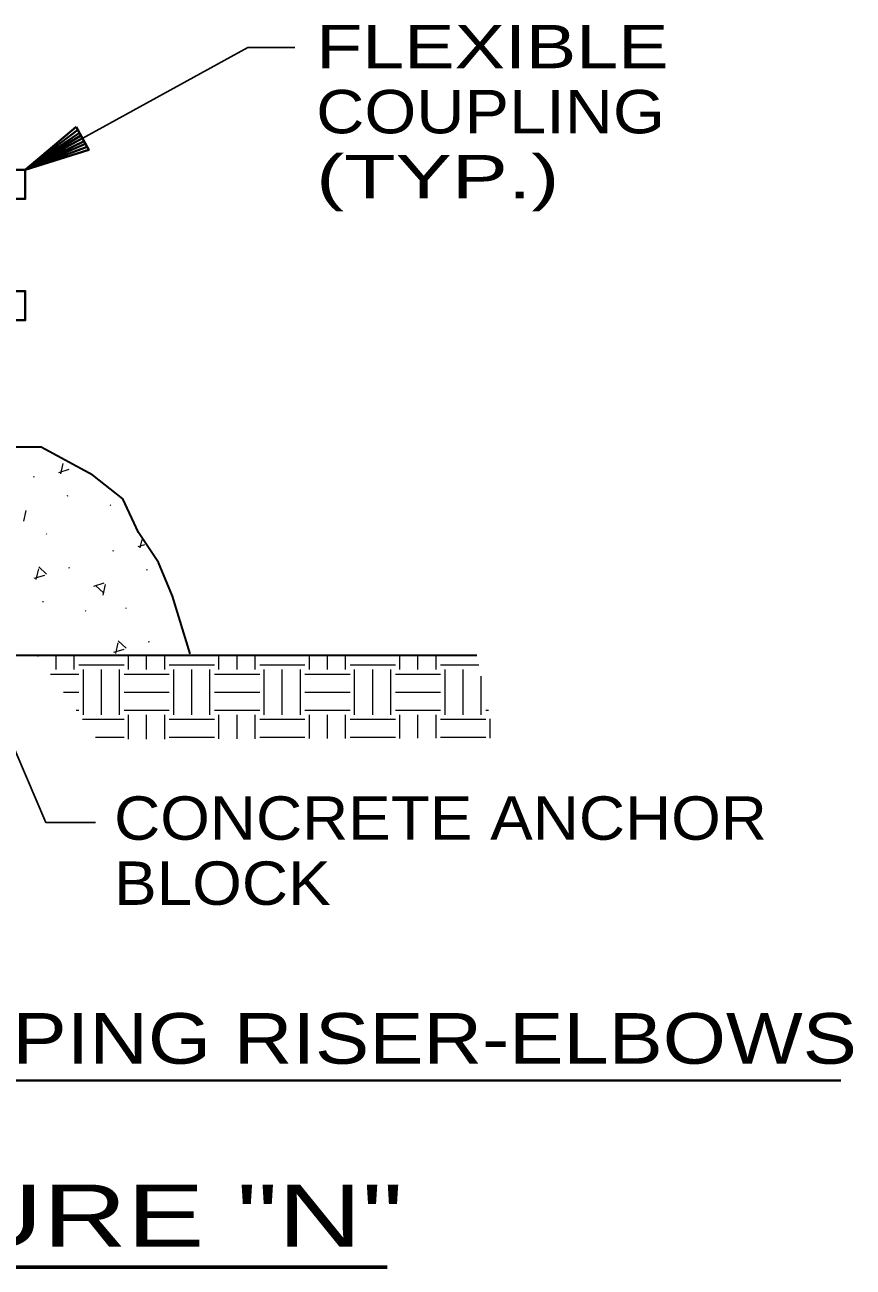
# Model space of a CAD drawing. Extents: x 55 to 190, y 198 to 264.
# Drawn here: x 95.8 to 100.64, y 210.74 to 218.01 of the extents above; entities that cross this region are included whole.
import ezdxf
from ezdxf.enums import TextEntityAlignment as Align

# ---------------------------------------------------------------- set-up
doc = ezdxf.new("R2010")
doc.units = 0
doc.header["$LTSCALE"] = 0.1
doc.layers.add('2', color=7, linetype='Continuous', lineweight=40)

msp = doc.modelspace()

# ---------------------------------------------------------------- linework, layer by layer
at = {"layer": '2'}
for p, q in [((95.7983, 217.1625), (96.1063, 217.3964)), ((95.7983, 217.1625), (96.1169, 217.3779)), ((95.7983, 217.1625), (96.1245, 217.3628)), ((96.1335, 217.3472), (95.7983, 217.1625)), ((95.7983, 217.1625), (96.1425, 217.3303)), ((95.7983, 217.1625), (96.1605, 217.2975)), ((91.1842, 211.8314), (100.5701, 211.8314))]:
    msp.add_line(p, q, dxfattribs=at)
at = {"layer": '2', "lineweight": 13}
for p, q in [((95.9946, 215.3906), (96.0552, 215.4091)), ((96.0182, 215.443), (96.0042, 215.3827)), ((95.8494, 215.3641), (95.8504, 215.3694)), ((96.0475, 215.2533), (96.0425, 215.2519)), ((95.7898, 215.1064), (95.8041, 215.1683)), ((96.2992, 215.1972), (96.2952, 215.2006)), ((95.9232, 215.0321), (95.9221, 215.0271)), ((96.459, 214.9572), (96.4992, 214.9694)), ((96.4804, 214.999), (96.469, 214.9495)), ((96.314, 214.931), (96.3153, 214.9363)), ((95.8756, 214.826), (95.8613, 214.7641)), ((95.9237, 214.7948), (95.8774, 214.8379)), ((96.0541, 214.8334), (96.0602, 214.8352)), ((96.5122, 214.8199), (96.5071, 214.8183)), ((95.8517, 214.7715), (95.9126, 214.79)), ((96.2589, 214.7426), (96.1984, 214.7241)), ((96.2544, 214.6733), (96.2687, 214.7352)), ((96.2097, 214.7286), (96.256, 214.6855)), ((95.9049, 214.6341), (95.8996, 214.6328)), ((96.3881, 214.599), (96.3867, 214.5939)), ((96.156, 214.5781), (96.1521, 214.5818)), ((96.3404, 214.3929), (96.3262, 214.3309)), ((96.3883, 214.3616), (96.3418, 214.4048)), ((96.5188, 214.4), (96.5248, 214.4019)), ((95.874, 214.3143), (95.874, 214.3246)), ((95.9798, 214.2375), (95.9798, 214.3246)), ((96.0856, 214.2375), (96.0856, 214.3246)), ((96.3164, 214.3381), (96.3769, 214.3566)), ((96.4031, 214.2375), (96.4031, 214.3246)), ((96.509, 214.2375), (96.509, 214.3246)), ((96.6148, 214.2375), (96.6148, 214.3246)), ((96.9323, 214.2375), (96.9323, 214.3246)), ((97.0381, 214.2375), (97.0381, 214.3246)), ((97.144, 214.2375), (97.144, 214.3246)), ((97.4615, 214.2375), (97.4615, 214.3246)), ((97.5673, 214.2375), (97.5673, 214.3246)), ((97.6731, 214.2375), (97.6731, 214.3246)), ((97.9906, 214.2375), (97.9906, 214.3246)), ((98.0965, 214.2375), (98.0965, 214.3246)), ((98.2023, 214.2375), (98.2023, 214.3246)), ((96.1121, 214.264), (96.3767, 214.264)), ((96.1386, 213.973), (96.1386, 214.2375)), ((96.2444, 213.973), (96.2444, 214.2375)), ((96.3502, 213.973), (96.3502, 214.2375)), ((96.6413, 214.264), (96.9059, 214.264)), ((96.6677, 213.973), (96.6677, 214.2375)), ((96.7736, 213.973), (96.7736, 214.2375)), ((96.8794, 213.973), (96.8794, 214.2375)), ((97.1704, 214.264), (97.435, 214.264)), ((97.1969, 213.973), (97.1969, 214.2375)), ((97.3027, 213.973), (97.3027, 214.2375)), ((97.4086, 213.973), (97.4086, 214.2375)), ((97.6996, 214.264), (97.9642, 214.264)), ((97.7261, 213.973), (97.7261, 214.2375)), ((97.8319, 213.973), (97.8319, 214.2375)), ((97.9377, 213.973), (97.9377, 214.2375)), ((98.2288, 214.264), (98.4531, 214.264)), ((98.2552, 213.973), (98.2552, 214.2375)), ((98.3611, 213.973), (98.3611, 214.2375)), ((95.9473, 214.2111), (96.1121, 214.2111)), ((96.3767, 214.2111), (96.6413, 214.2111)), ((96.9059, 214.2111), (97.1704, 214.2111)), ((97.435, 214.2111), (97.6996, 214.2111)), ((97.9642, 214.2111), (98.2288, 214.2111)), ((98.4669, 213.973), (98.4669, 214.1984)), ((96.0221, 214.1053), (96.1121, 214.1053)), ((96.3767, 214.1053), (96.6413, 214.1053)), ((96.9059, 214.1053), (97.1704, 214.1053)), ((97.435, 214.1053), (97.6996, 214.1053)), ((97.9642, 214.1053), (98.2288, 214.1053)), ((96.097, 213.9994), (96.1121, 213.9994)), ((96.1346, 213.9465), (96.3767, 213.9465)), ((96.3767, 213.9994), (96.6413, 213.9994)), ((96.4031, 213.8296), (96.4031, 213.973)), ((96.509, 213.8298), (96.509, 213.973)), ((96.6148, 213.8304), (96.6148, 213.973)), ((96.6413, 213.9465), (96.9059, 213.9465)), ((96.9059, 213.9994), (97.1704, 213.9994)), ((96.9323, 213.8311), (96.9323, 213.973)), ((97.0381, 213.8314), (97.0381, 213.973)), ((97.144, 213.8319), (97.144, 213.973)), ((97.1704, 213.9465), (97.435, 213.9465)), ((97.435, 213.9994), (97.6996, 213.9994)), ((97.4615, 213.8327), (97.4615, 213.973)), ((97.5673, 213.833), (97.5673, 213.973)), ((97.6731, 213.8335), (97.6731, 213.973)), ((97.6996, 213.9465), (97.9642, 213.9465)), ((97.9642, 213.9994), (98.2288, 213.9994)), ((97.9906, 213.8343), (97.9906, 213.973)), ((98.0965, 213.8346), (98.0965, 213.973)), ((98.2023, 213.8351), (98.2023, 213.973)), ((98.2288, 213.9465), (98.4934, 213.9465)), ((98.4934, 213.9994), (98.509, 213.9994)), ((98.5198, 213.8359), (98.5198, 213.9478)), ((96.2097, 213.8407), (96.3767, 213.8407)), ((96.6413, 213.8407), (96.9059, 213.8407)), ((97.1704, 213.8407), (97.435, 213.8407)), ((97.6996, 213.8407), (97.9642, 213.8407)), ((98.2288, 213.8407), (98.4934, 213.8407))]:
    msp.add_line(p, q, dxfattribs=at)
at = {"layer": '2', "lineweight": 35}
msp.add_line((92.0375, 214.3211), (98.441, 214.3211), dxfattribs=at)
at = {"layer": '2', "lineweight": 60}
msp.add_line((94.0616, 210.7392), (97.9168, 210.7392), dxfattribs=at)
at = {"layer": '2', "lineweight": 25}
for points in [[(97.3752, 217.8782), (97.1016, 217.8782), (95.7983, 217.1625)], [(96.2105, 213.3411), (95.9198, 213.3411), (95.5094, 214.2987)]]:
    msp.add_lwpolyline(points, dxfattribs=at)
at = {"layer": '2'}
for points in [[(96.0968, 217.4133), (96.1703, 217.2792), (95.7983, 217.1625)], [(96.0968, 217.4133), (95.7983, 217.1625), (96.1518, 217.3139)]]:
    msp.add_lwpolyline(points, dxfattribs=at)
for points in [[(94.5114, 216.9916), (95.7983, 216.9916), (95.7983, 217.1625), (94.5114, 217.1625)], [(94.5114, 216.2815), (95.7983, 216.2815), (95.7983, 216.4524), (94.5114, 216.4524)]]:
    msp.add_lwpolyline(points, close=True, dxfattribs=at)
at = {"layer": '2', "lineweight": 35}
msp.add_lwpolyline([(96.7643, 214.3296), (96.6598, 214.6664), (96.5783, 214.8641), (96.4621, 215.0384), (96.3693, 215.2361), (96.1949, 215.3755), (95.8928, 215.5382), (95.6255, 215.5382), (95.4162, 215.5496), (95.207, 215.48), (94.9863, 215.3755), (94.8119, 215.1662), (94.6725, 214.9223), (94.5564, 214.6781), (94.4823, 214.3211)], dxfattribs=at)

# ---------------------------------------------------------------- texts
at = {"layer": '2'}
for s, width, p in [('FLEXIBLE', 1.3, (97.5009, 217.7568)), ('COUPLING', 1.15, (97.5009, 217.3758)), ('(TYP.)', 1.45, (97.5009, 216.9948)), ('CONCRETE ANCHOR', 1.1, (96.3187, 213.2409)), ('BLOCK', 1.1, (96.3187, 212.8599))]:
    msp.add_text(s, height=0.254, dxfattribs=dict(at, width=width)).set_placement(p)
for s, height, width, p in [('UNDERGROUND PIPING RISER-ELBOWS', 0.2963, 1.2, (96.0018, 211.9299)), ('FIGURE "N"', 0.3633, 1.4, (96.1437, 210.8593))]:
    msp.add_text(s, height=height, dxfattribs=dict(at, width=width)).set_placement(p, align=Align.CENTER)

doc.saveas('drawing.dxf')
